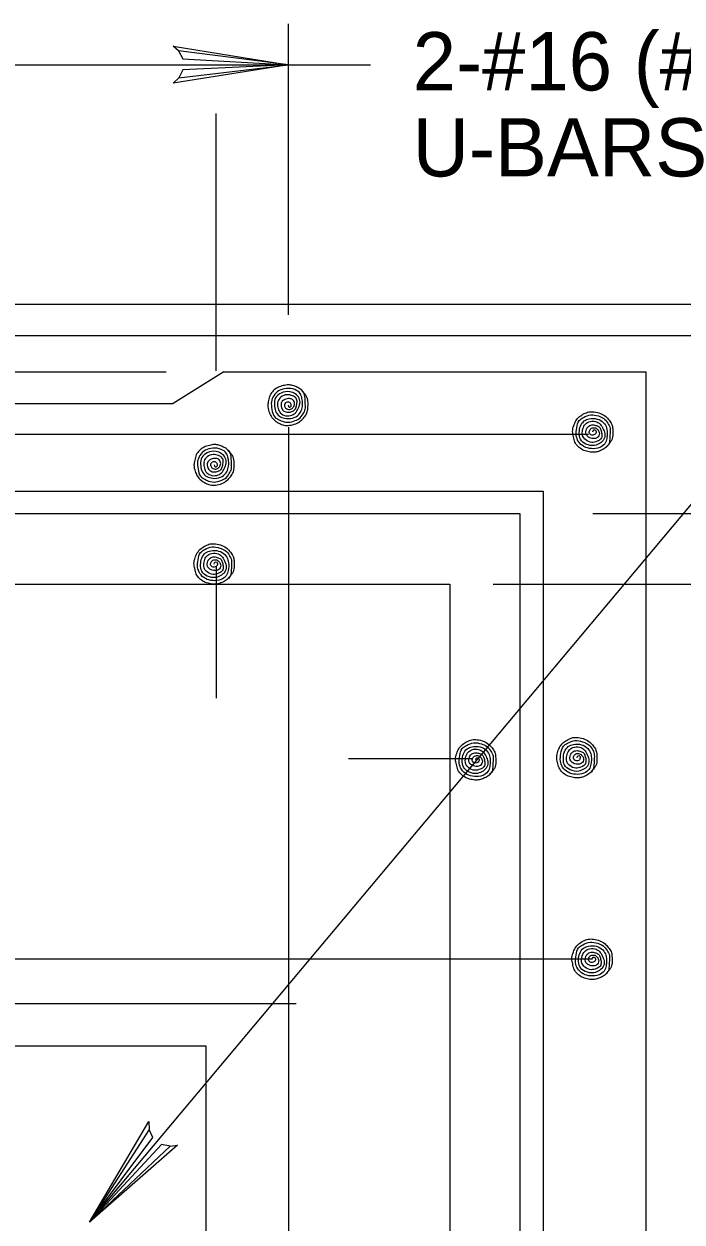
# Model space of a CAD drawing. Extents: x 638455 to 640199, y 298558 to 299152.
# Drawn here: x 639502.8 to 639540.7, y 299012.9 to 299081.9 of the extents above; entities that cross this region are included whole.
import ezdxf

# ---------------------------------------------------------------- set-up
doc = ezdxf.new("R2010")
doc.units = 0
for name, color, linetype in [('1', 7, 'Continuous'), ('2', 7, 'Continuous'), ('3', 7, 'Continuous')]:
    doc.layers.add(name, color=color, linetype=linetype)

msp = doc.modelspace()

# ---------------------------------------------------------------- linework, layer by layer
at = {"layer": '1'}
for p, q in [((639506.575, 299012.867), (639564.155, 299081.549)), ((639514.332, 299061.884), (639511.411, 299060.066))]:
    msp.add_line(p, q, dxfattribs=at)
at = {"layer": '2'}
for p, q in [((639518.052, 299065.177), (639518.052, 299081.944)), ((639480.579, 299079.596), (639518.052, 299079.596)), ((639518.052, 299079.596), (639522.777, 299079.596)), ((639513.883, 299061.942), (639513.883, 299076.774)), ((639455.114, 299065.791), (639543.517, 299065.791)), ((639514.332, 299061.884), (639538.663, 299061.884)), ((639538.663, 299061.884), (639538.663, 298949.406)), ((639486.183, 299060.066), (639511.411, 299060.066)), ((639518.052, 299058.705), (639518.052, 298996.906)), ((639463.941, 299058.292), (639535.345, 299058.292)), ((639465.9, 299055.006), (639532.731, 299055.006)), ((639532.731, 299055.006), (639532.731, 298956.209)), ((639467.242, 299053.726), (639531.389, 299053.726)), ((639531.389, 299053.726), (639531.389, 298957.614)), ((639535.593, 299053.726), (639605.716, 299053.726)), ((639513.883, 299050.686), (639513.883, 299043.062)), ((639471.267, 299049.639), (639527.364, 299049.639)), ((639527.364, 299049.639), (639527.364, 298961.576)), ((639529.862, 299049.639), (639621, 299049.639)), ((639521.523, 299039.596), (639528.647, 299039.596)), ((639500.102, 299028.043), (639535.572, 299028.043)), ((639518.499, 299025.445), (639479.119, 299025.445)), ((639373.945, 299023.031), (639513.286, 299023.031)), ((639513.286, 299023.031), (639513.286, 298988.183))]:
    msp.add_line(p, q, dxfattribs=at)
for points in [[(639511.722, 299080.391), (639511.96, 299079.933), (639518.052, 299079.596), (639511.722, 299080.391), (639511.399, 299080.67), (639518.052, 299079.596), (639511.962, 299079.296), (639511.742, 299078.841), (639518.052, 299079.596), (639511.399, 299078.539), (639511.742, 299078.841)], [(639456.919, 299063.987), (639543.517, 299063.987)], [(639459.977, 299061.884), (639511.013, 299061.884)], [(639511.228, 299017.233), (639510.725, 299017.34), (639506.576, 299012.867), (639511.228, 299017.233), (639511.648, 299017.302), (639506.576, 299012.867), (639510.232, 299017.746), (639510.024, 299018.205), (639506.576, 299012.867), (639510.01, 299018.662), (639510.024, 299018.205)]]:
    msp.add_lwpolyline(points, dxfattribs=at)
for points in [[(639518.031, 299059.967), (639518.089, 299059.851), (639518.177, 299059.866), (639518.194, 299060.048), (639518.034, 299060.144), (639517.84, 299060.048), (639517.848, 299059.866), (639517.953, 299059.752), (639518.177, 299059.735), (639518.328, 299059.851), (639518.406, 299060.04), (639518.293, 299060.287), (639518.052, 299060.342), (639517.784, 299060.26), (639517.642, 299060.092), (639517.66, 299059.807), (639517.793, 299059.624), (639518.034, 299059.558), (639518.249, 299059.601), (639518.426, 299059.708), (639518.502, 299059.894), (639518.548, 299060.135), (639518.493, 299060.359), (639518.284, 299060.501), (639517.962, 299060.565), (639517.616, 299060.423), (639517.442, 299060.182), (639517.442, 299059.851), (639517.552, 299059.569), (639517.793, 299059.383), (639518.177, 299059.36), (639518.449, 299059.511), (639518.615, 299059.775), (639518.714, 299060.048), (639518.667, 299060.376), (639518.449, 299060.609), (639518.133, 299060.742), (639517.627, 299060.664), (639517.311, 299060.385), (639517.244, 299060.002), (639517.311, 299059.624), (639517.532, 299059.328), (639517.825, 299059.209), (639518.284, 299059.218), (639518.647, 299059.427), (639518.818, 299059.735), (639518.865, 299060.06), (639518.833, 299060.342), (639518.722, 299060.643), (639518.426, 299060.859), (639517.944, 299060.925), (639517.517, 299060.806), (639517.201, 299060.51), (639517.07, 299060.164), (639517.102, 299059.72), (639517.244, 299059.308), (639517.485, 299059.133), (639517.91, 299058.98), (639518.351, 299059.044), (639518.658, 299059.186), (639518.894, 299059.459), (639519.021, 299059.743), (639519.021, 299060.048), (639519.007, 299060.376), (639518.931, 299060.684), (639518.775, 299060.859), (639518.534, 299061.01), (639518.293, 299061.1), (639518.052, 299061.134), (639517.75, 299061.091), (639517.442, 299060.992), (639517.178, 299060.797), (639516.995, 299060.548), (639516.907, 299060.234), (639516.861, 299059.941), (639516.928, 299059.601), (639517.05, 299059.328), (639517.267, 299059.078), (639517.532, 299058.91), (639517.793, 299058.811), (639518.107, 299058.802), (639518.473, 299058.893), (639518.775, 299059.078), (639518.963, 299059.276), (639519.117, 299059.525), (639519.173, 299059.79), (639519.181, 299060.092), (639519.117, 299060.423), (639519.021, 299060.574), (639518.818, 299060.797)], [(639535.602, 299058.418), (639535.66, 299058.534), (639535.75, 299058.52), (639535.767, 299058.337), (639535.608, 299058.238), (639535.41, 299058.337), (639535.419, 299058.52), (639535.526, 299058.63), (639535.75, 299058.65), (639535.901, 299058.534), (639535.976, 299058.345), (639535.866, 299058.096), (639535.625, 299058.043), (639535.358, 299058.121), (639535.212, 299058.293), (639535.233, 299058.578), (639535.366, 299058.761), (639535.608, 299058.827), (639535.82, 299058.784), (639535.999, 299058.676), (639536.075, 299058.488), (639536.119, 299058.247), (639536.066, 299058.023), (639535.857, 299057.881), (639535.535, 299057.82), (639535.187, 299057.962), (639535.012, 299058.203), (639535.012, 299058.534), (639535.125, 299058.813), (639535.366, 299059.001), (639535.75, 299059.025), (639536.02, 299058.871), (639536.185, 299058.61), (639536.284, 299058.337), (639536.241, 299058.005), (639536.02, 299057.773), (639535.703, 299057.64), (639535.201, 299057.721), (639534.885, 299057.997), (639534.818, 299058.38), (639534.885, 299058.761), (639535.102, 299059.054), (639535.396, 299059.176), (639535.857, 299059.167), (639536.217, 299058.955), (639536.392, 299058.65), (639536.435, 299058.322), (639536.403, 299058.043), (639536.293, 299057.738), (639535.999, 299057.524), (639535.517, 299057.457), (639535.088, 299057.579), (639534.771, 299057.872), (639534.643, 299058.22), (639534.675, 299058.662), (639534.818, 299059.077), (639535.059, 299059.251), (639535.483, 299059.402), (639535.924, 299059.341), (639536.232, 299059.196), (639536.467, 299058.926), (639536.592, 299058.638), (639536.592, 299058.337), (639536.577, 299058.005), (639536.502, 299057.698), (639536.348, 299057.524), (639536.107, 299057.373), (639535.866, 299057.282), (639535.625, 299057.248), (639535.32, 299057.294), (639535.012, 299057.39), (639534.751, 299057.587), (639534.568, 299057.837), (639534.478, 299058.148), (639534.434, 299058.444), (639534.501, 299058.784), (639534.62, 299059.054), (639534.838, 299059.304), (639535.102, 299059.475), (639535.366, 299059.571), (639535.677, 299059.582), (639536.043, 299059.493), (639536.348, 299059.304), (639536.534, 299059.109), (639536.691, 299058.859), (639536.743, 299058.595), (639536.752, 299058.293), (639536.691, 299057.962), (639536.592, 299057.811), (639536.392, 299057.587)], [(639513.774, 299056.524), (639513.835, 299056.408), (639513.922, 299056.422), (639513.94, 299056.605), (639513.78, 299056.701), (639513.583, 299056.605), (639513.591, 299056.422), (639513.699, 299056.309), (639513.922, 299056.291), (639514.073, 299056.408), (639514.149, 299056.596), (639514.039, 299056.843), (639513.797, 299056.898), (639513.53, 299056.817), (639513.388, 299056.648), (639513.405, 299056.364), (639513.539, 299056.181), (639513.78, 299056.114), (639513.995, 299056.158), (639514.172, 299056.265), (639514.248, 299056.451), (639514.294, 299056.692), (639514.239, 299056.916), (639514.03, 299057.058), (639513.707, 299057.122), (639513.362, 299056.98), (639513.187, 299056.739), (639513.187, 299056.408), (639513.298, 299056.126), (639513.539, 299055.94), (639513.922, 299055.917), (639514.195, 299056.068), (639514.361, 299056.332), (639514.46, 299056.605), (639514.413, 299056.933), (639514.195, 299057.165), (639513.879, 299057.299), (639513.374, 299057.221), (639513.057, 299056.942), (639512.99, 299056.559), (639513.057, 299056.181), (639513.278, 299055.885), (639513.571, 299055.766), (639514.03, 299055.774), (639514.393, 299055.983), (639514.564, 299056.291), (639514.611, 299056.617), (639514.579, 299056.898), (639514.468, 299057.2), (639514.172, 299057.415), (639513.69, 299057.482), (639513.263, 299057.363), (639512.947, 299057.067), (639512.816, 299056.718), (639512.848, 299056.277), (639512.99, 299055.864), (639513.231, 299055.69), (639513.655, 299055.537), (639514.097, 299055.6), (639514.405, 299055.743), (639514.639, 299056.016), (639514.768, 299056.3), (639514.768, 299056.605), (639514.753, 299056.933), (639514.677, 299057.241), (639514.521, 299057.415), (639514.279, 299057.566), (639514.039, 299057.657), (639513.797, 299057.691), (639513.495, 299057.648), (639513.187, 299057.549), (639512.923, 299057.354), (639512.74, 299057.105), (639512.65, 299056.791), (639512.607, 299056.497), (639512.673, 299056.158), (639512.796, 299055.885), (639513.013, 299055.635), (639513.278, 299055.467), (639513.539, 299055.368), (639513.853, 299055.359), (639514.218, 299055.449), (639514.521, 299055.635), (639514.706, 299055.833), (639514.863, 299056.082), (639514.918, 299056.344), (639514.927, 299056.648), (639514.863, 299056.98), (639514.768, 299057.131), (639514.564, 299057.354)], [(639513.774, 299050.806), (639513.835, 299050.922), (639513.922, 299050.907), (639513.94, 299050.725), (639513.78, 299050.629), (639513.583, 299050.725), (639513.591, 299050.907), (639513.699, 299051.021), (639513.922, 299051.038), (639514.073, 299050.922), (639514.149, 299050.733), (639514.039, 299050.486), (639513.797, 299050.431), (639513.53, 299050.513), (639513.388, 299050.681), (639513.405, 299050.966), (639513.539, 299051.149), (639513.78, 299051.215), (639513.995, 299051.172), (639514.172, 299051.064), (639514.248, 299050.878), (639514.294, 299050.638), (639514.239, 299050.414), (639514.03, 299050.272), (639513.707, 299050.208), (639513.362, 299050.35), (639513.187, 299050.591), (639513.187, 299050.922), (639513.298, 299051.204), (639513.539, 299051.39), (639513.922, 299051.413), (639514.195, 299051.262), (639514.361, 299050.998), (639514.46, 299050.725), (639514.413, 299050.397), (639514.195, 299050.164), (639513.879, 299050.031), (639513.374, 299050.109), (639513.057, 299050.388), (639512.99, 299050.771), (639513.057, 299051.149), (639513.278, 299051.445), (639513.571, 299051.564), (639514.03, 299051.555), (639514.393, 299051.346), (639514.564, 299051.038), (639514.611, 299050.713), (639514.579, 299050.431), (639514.468, 299050.129), (639514.172, 299049.914), (639513.69, 299049.848), (639513.263, 299049.967), (639512.947, 299050.263), (639512.816, 299050.611), (639512.848, 299051.053), (639512.99, 299051.465), (639513.231, 299051.639), (639513.655, 299051.793), (639514.097, 299051.729), (639514.405, 299051.587), (639514.639, 299051.314), (639514.768, 299051.03), (639514.768, 299050.725), (639514.753, 299050.397), (639514.677, 299050.089), (639514.521, 299049.914), (639514.279, 299049.763), (639514.039, 299049.673), (639513.797, 299049.639), (639513.495, 299049.682), (639513.187, 299049.781), (639512.923, 299049.975), (639512.74, 299050.225), (639512.65, 299050.539), (639512.607, 299050.832), (639512.673, 299051.172), (639512.796, 299051.445), (639513.013, 299051.695), (639513.278, 299051.863), (639513.539, 299051.962), (639513.853, 299051.971), (639514.218, 299051.88), (639514.521, 299051.695), (639514.706, 299051.497), (639514.863, 299051.248), (639514.918, 299050.986), (639514.927, 299050.681), (639514.863, 299050.35), (639514.768, 299050.199), (639514.564, 299049.975)], [(639528.857, 299039.513), (639528.915, 299039.629), (639529.005, 299039.614), (639529.022, 299039.432), (639528.86, 299039.333), (639528.665, 299039.432), (639528.674, 299039.614), (639528.782, 299039.728), (639529.005, 299039.745), (639529.156, 299039.629), (639529.232, 299039.44), (639529.118, 299039.191), (639528.877, 299039.138), (639528.61, 299039.22), (639528.468, 299039.388), (639528.485, 299039.672), (639528.619, 299039.856), (639528.86, 299039.922), (639529.075, 299039.879), (639529.252, 299039.771), (639529.33, 299039.586), (639529.374, 299039.345), (639529.322, 299039.121), (639529.11, 299038.979), (639528.79, 299038.915), (639528.442, 299039.057), (639528.268, 299039.298), (639528.268, 299039.629), (639528.381, 299039.911), (639528.619, 299040.097), (639529.005, 299040.12), (639529.275, 299039.969), (639529.441, 299039.705), (639529.539, 299039.432), (639529.496, 299039.103), (639529.275, 299038.871), (639528.959, 299038.737), (639528.456, 299038.816), (639528.137, 299039.095), (639528.07, 299039.478), (639528.137, 299039.856), (639528.357, 299040.152), (639528.651, 299040.271), (639529.11, 299040.262), (639529.473, 299040.053), (639529.647, 299039.745), (639529.69, 299039.42), (639529.659, 299039.138), (639529.548, 299038.836), (639529.252, 299038.621), (639528.773, 299038.555), (639528.343, 299038.674), (639528.026, 299038.97), (639527.899, 299039.315), (639527.928, 299039.757), (639528.07, 299040.172), (639528.311, 299040.346), (639528.735, 299040.497), (639529.176, 299040.436), (639529.484, 299040.294), (639529.722, 299040.021), (639529.847, 299039.737), (639529.847, 299039.432), (639529.833, 299039.103), (639529.757, 299038.796), (639529.6, 299038.621), (639529.359, 299038.47), (639529.118, 299038.38), (639528.877, 299038.346), (639528.575, 299038.389), (639528.268, 299038.488), (639528.003, 299038.682), (639527.823, 299038.932), (639527.733, 299039.246), (639527.687, 299039.539), (639527.754, 299039.879), (639527.875, 299040.152), (639528.093, 299040.402), (639528.357, 299040.57), (639528.619, 299040.669), (639528.933, 299040.678), (639529.299, 299040.587), (639529.6, 299040.402), (639529.789, 299040.204), (639529.946, 299039.955), (639529.998, 299039.69), (639530.007, 299039.388), (639529.946, 299039.057), (639529.847, 299038.906), (639529.647, 299038.682)], [(639534.687, 299039.638), (639534.745, 299039.754), (639534.835, 299039.739), (639534.852, 299039.557), (639534.69, 299039.458), (639534.495, 299039.557), (639534.504, 299039.739), (639534.611, 299039.853), (639534.835, 299039.87), (639534.986, 299039.754), (639535.061, 299039.565), (639534.948, 299039.316), (639534.707, 299039.263), (639534.44, 299039.345), (639534.298, 299039.513), (639534.315, 299039.797), (639534.448, 299039.981), (639534.69, 299040.047), (639534.905, 299040.004), (639535.082, 299039.896), (639535.16, 299039.711), (639535.204, 299039.47), (639535.151, 299039.246), (639534.939, 299039.104), (639534.62, 299039.04), (639534.271, 299039.182), (639534.097, 299039.423), (639534.097, 299039.754), (639534.21, 299040.036), (639534.448, 299040.222), (639534.835, 299040.245), (639535.105, 299040.094), (639535.27, 299039.83), (639535.369, 299039.557), (639535.326, 299039.228), (639535.105, 299038.996), (639534.788, 299038.862), (639534.286, 299038.941), (639533.967, 299039.22), (639533.9, 299039.603), (639533.967, 299039.981), (639534.187, 299040.277), (639534.481, 299040.396), (639534.939, 299040.387), (639535.302, 299040.178), (639535.477, 299039.87), (639535.52, 299039.545), (639535.488, 299039.263), (639535.378, 299038.961), (639535.082, 299038.746), (639534.602, 299038.68), (639534.173, 299038.799), (639533.856, 299039.095), (639533.729, 299039.44), (639533.758, 299039.882), (639533.9, 299040.297), (639534.141, 299040.471), (639534.565, 299040.622), (639535.006, 299040.561), (639535.314, 299040.419), (639535.552, 299040.146), (639535.677, 299039.862), (639535.677, 299039.557), (639535.662, 299039.228), (639535.587, 299038.921), (639535.43, 299038.746), (639535.189, 299038.595), (639534.948, 299038.505), (639534.707, 299038.471), (639534.405, 299038.514), (639534.097, 299038.613), (639533.833, 299038.807), (639533.653, 299039.057), (639533.563, 299039.371), (639533.517, 299039.664), (639533.583, 299040.004), (639533.705, 299040.277), (639533.923, 299040.527), (639534.187, 299040.695), (639534.448, 299040.794), (639534.762, 299040.803), (639535.128, 299040.712), (639535.43, 299040.527), (639535.619, 299040.329), (639535.776, 299040.08), (639535.828, 299039.815), (639535.837, 299039.513), (639535.776, 299039.182), (639535.677, 299039.031), (639535.477, 299038.807)], [(639535.561, 299028.014), (639535.619, 299028.13), (639535.709, 299028.115), (639535.727, 299027.933), (639535.564, 299027.834), (639535.369, 299027.933), (639535.378, 299028.115), (639535.486, 299028.229), (639535.709, 299028.246), (639535.86, 299028.13), (639535.936, 299027.941), (639535.823, 299027.692), (639535.581, 299027.639), (639535.314, 299027.721), (639535.172, 299027.889), (639535.19, 299028.173), (639535.323, 299028.357), (639535.564, 299028.423), (639535.779, 299028.38), (639535.956, 299028.272), (639536.034, 299028.087), (639536.078, 299027.846), (639536.026, 299027.622), (639535.814, 299027.48), (639535.495, 299027.416), (639535.146, 299027.558), (639534.972, 299027.799), (639534.972, 299028.13), (639535.085, 299028.412), (639535.323, 299028.598), (639535.709, 299028.621), (639535.979, 299028.47), (639536.145, 299028.206), (639536.244, 299027.933), (639536.2, 299027.604), (639535.979, 299027.372), (639535.663, 299027.238), (639535.16, 299027.317), (639534.841, 299027.596), (639534.774, 299027.979), (639534.841, 299028.357), (639535.062, 299028.653), (639535.355, 299028.772), (639535.814, 299028.763), (639536.177, 299028.554), (639536.351, 299028.246), (639536.395, 299027.921), (639536.363, 299027.639), (639536.252, 299027.337), (639535.956, 299027.122), (639535.477, 299027.056), (639535.047, 299027.175), (639534.731, 299027.471), (639534.603, 299027.816), (639534.632, 299028.258), (639534.774, 299028.673), (639535.015, 299028.847), (639535.439, 299028.998), (639535.881, 299028.937), (639536.188, 299028.795), (639536.427, 299028.522), (639536.551, 299028.238), (639536.551, 299027.933), (639536.537, 299027.604), (639536.461, 299027.297), (639536.305, 299027.122), (639536.064, 299026.971), (639535.823, 299026.881), (639535.581, 299026.847), (639535.28, 299026.89), (639534.972, 299026.989), (639534.708, 299027.183), (639534.527, 299027.433), (639534.437, 299027.747), (639534.391, 299028.04), (639534.458, 299028.38), (639534.58, 299028.653), (639534.797, 299028.903), (639535.062, 299029.071), (639535.323, 299029.17), (639535.637, 299029.179), (639536.003, 299029.088), (639536.305, 299028.903), (639536.493, 299028.705), (639536.65, 299028.456), (639536.702, 299028.191), (639536.711, 299027.889), (639536.65, 299027.558), (639536.551, 299027.407), (639536.351, 299027.183)]]:
    msp.add_spline(points, degree=3, dxfattribs=at)

# ---------------------------------------------------------------- texts
at = {"layer": '3'}
for s, p in [('2-#16 (#5)', (639525.217, 299078.111)), ('U-BARS', (639525.217, 299073.151))]:
    msp.add_text(s, height=3.36, dxfattribs=at).set_placement(p)

doc.saveas('drawing.dxf')
